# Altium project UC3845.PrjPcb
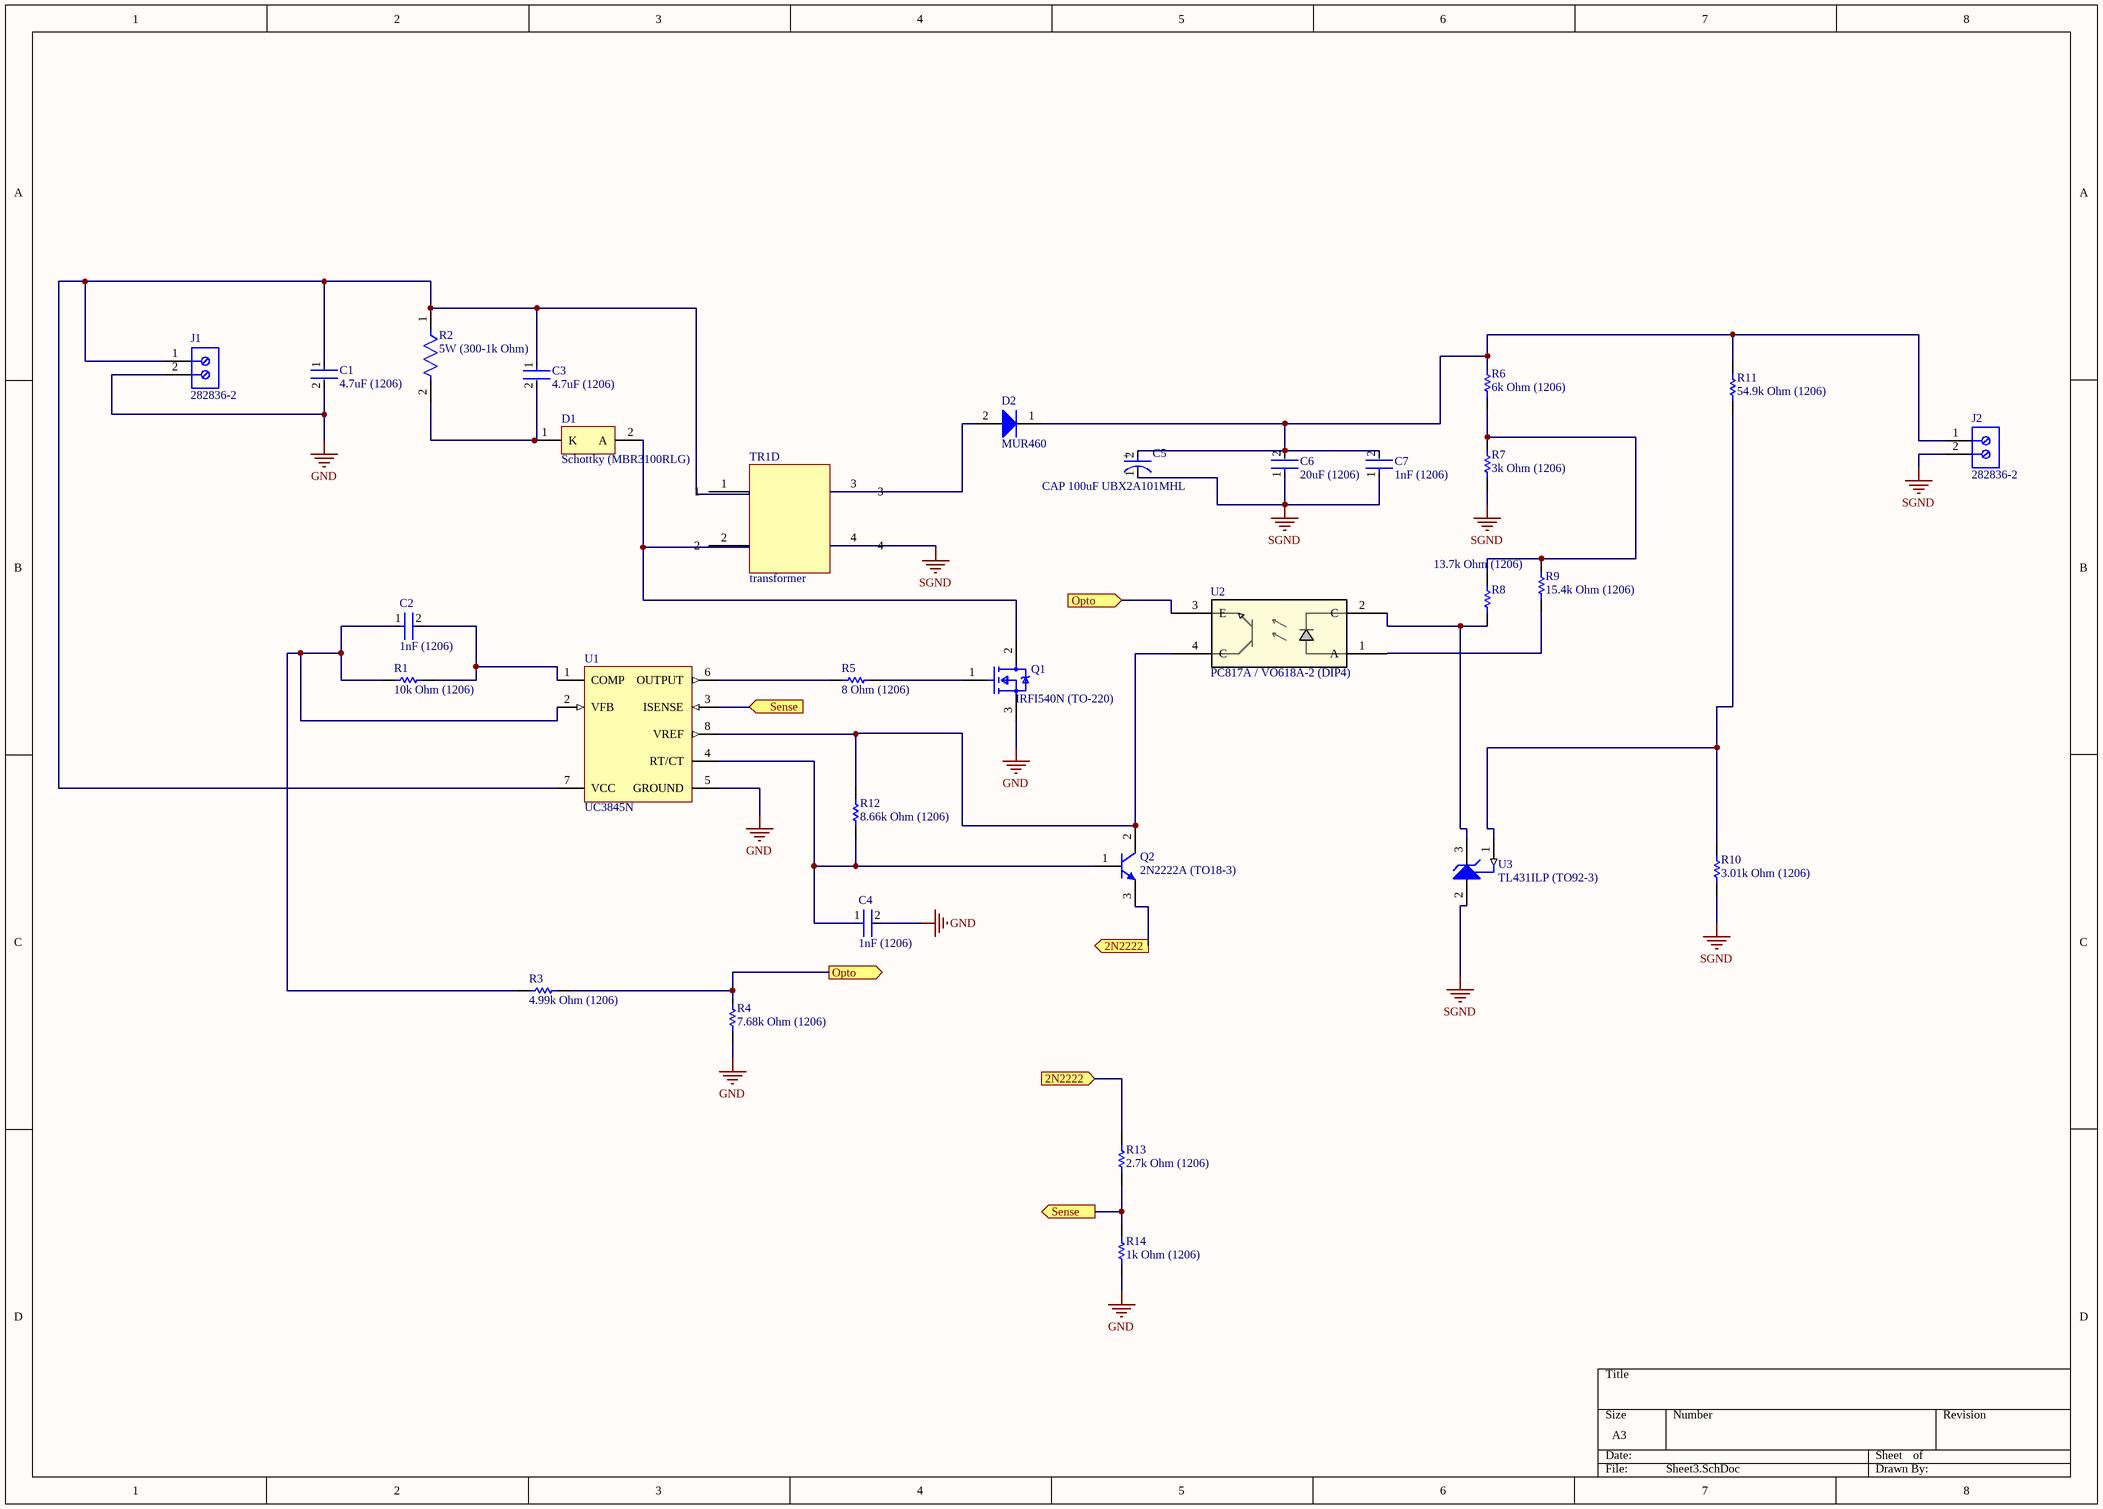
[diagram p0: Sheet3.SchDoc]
1 sheet, 31 parts. Net scope: flat (ports and power ports of the same name join across sheets).
Board file: PCB_v2.PcbDoc

## Sheet Sheet3.SchDoc
size A3

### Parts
C1  4.7uF (1206)  [FP-C1206C-EB-MFG]
C2  1nF (1206)  [FP-C1206C-EB-MFG]
C3  4.7uF (1206)  [FP-C1206C-EB-MFG]
C4  1nF (1206)  [FP-C1206C-EB-MFG]
C5  CAP 100uF UBX2A101MHL  [FP-UBX2A101MHL-MFG]
C6  20uF (1206)  [FP-C1206C-EB-MFG]
C7  1nF (1206)  [FP-C1206C-EB-MFG]
D1  Schottky (MBR3100RLG)  [ONSC-AXIAL_LEAD-2-267-05_V]
D2  MUR460  [ONSC-AXIAL_LEAD-2-267-05_V]
J1  282836-2  [TECO-282836-2_V]
J2  282836-2  [TECO-282836-2_V]
Q1  IRFI540N (TO-220)  [FP-PG-TO220-3-MFG]
Q2  2N2222A (TO18-3)  [STM-TO-18-3]
R1  10k Ohm (1206)  [RESC3216X60X45NL10T20]
R2  5W (300-1k Ohm)  [FP-SQP500-MFG]
R3  4.99k Ohm (1206)  [RESC3216X60X45NL10T20]
R4  7.68k Ohm (1206)  [RESC3216X60X45NL10T20]
R5  8 Ohm (1206)  [RESC3216X60X45NL10T20]
R6  6k Ohm (1206)  [RESC3216X60X45NL10T20]
R7  3k Ohm (1206)  [RESC3216X60X45NL10T20]
R8  13.7k Ohm (1206)  [RESC3216X60X45NL10T20]
R9  15.4k Ohm (1206)  [RESC3216X60X45NL10T20]
R10  3.01k Ohm (1206)  [RESC3216X60X45NL10T20]
R11  54.9k Ohm (1206)  [RESC3216X60X45NL10T20]
R12  8.66k Ohm (1206)  [RESC3216X60X45NL10T20]
R13  2.7k Ohm (1206)  [RESC3216X60X45NL10T20]
R14  1k Ohm (1206)  [RESC3216X60X45NL10T20]
TR1  transformer  [Transformer_flyback]  (part D of 4)
U1  UC3845N  [P0008A]
U2  PC817A / VO618A-2 (DIP4)  [DIP-4_VO618A_VIS]
U3  TL431ILP (TO92-3)  [LP0003A]

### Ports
2N2222 (in), 2N2222 (out), Opto (in), Opto (out), Sense (in), Sense (out)

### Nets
GND: C1.2 C4.2 J1.2 Q1.3(S) R4.1 R14.1 U1.5(GROUND)
SGND: C5.1(C) C6.1 C7.1 J2.2 R7.2 R10.2 TR1.4 U3.2(ANODE)
NetC1_1: C1.1 C3.1 J1.1 R2.1 TR1.1 U1.7(VCC)
NetC2_1: C2.1 R1.2 R3.2 U1.2(VFB)
NetC2_2: C2.2 R1.1 U1.1(COMP)
NetC3_2: C3.2 D1.1(K) R2.2
NetC4_1: C4.1 Q2.1(B) R12.2 U1.4(RT/CT)
NetC5_2: C5.2(A) C6.2 C7.2 D2.1(K) J2.1 R6.1 R11.1
NetD1_2: D1.2(A) Q1.2(D) TR1.2
NetD2_2: D2.2(A) TR1.3
NetQ1_1: Q1.1(G) R5.1
NetQ2_2: Q2.2(C) R12.1 U1.8(VREF) U2.4(C)
NetQ2_3: Q2.3(E) R13.1 ; port 2N2222
NetR3_1: R3.1 R4.2 U2.3(E) ; port Opto
NetR5_2: R5.2 U1.6(OUTPUT)
NetR6_2: R6.2 R7.1 R8.1 R9.1
NetR8_2: R8.2 U2.2(C) U3.3(CATHODE)
NetR9_2: R9.2 U2.1(A)
NetR10_1: R10.1 R11.2 U3.1(REF)
NetR13_2: R13.2 R14.2 U1.3(ISENSE) ; port Sense

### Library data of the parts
C1-C4 C6 C7 = CMP-03020-000955-1: Multilayer Ceramic Capacitor, C Series, 1000 Pf, - 5%, C0g / Np0, 100 V, 1206 [3216 Metric] Rohs Compliant: Yes; Manufacturer: KEMET; Manufacturer Part Number: C1206C102J1GACTU; Capacitance: 1,000 pF; Voltage Rating: 100 V; Tolerance: 0.05; Automotive Grade: Grade 0; Temperature Coefficient: 15%; Value: 1,000 pF
C5 = CMP-12462-000004-1: CAP ALUM 100UF 20% 100V RADIAL; Manufacturer: Nichicon; Material: Aluminum; Automotive Grade: Grade 0; Ripple Current: 950mA; Leakage Current: 300uA; Life: 1000Hours; Dissipation Factor: 8%
D1 = CMP-1055-00020-1: Rectifier, 2-Pin Axial_Lead, Pb-Free, Tape and Reel; Manufacturer: On Semiconductor; Configuration: Single; IFSM Max (A): 150
D2 = CMP-0902-00067-1: SWITCHMODE(TM) Power Rectifier, 2-Pin Axial_Lead, Pb-Free, Bulk Bag; Manufacturer: On Semiconductor; IFSM Max (A): 110; Type: Ultrafast; VRRM Max (V): 600
J1 J2 = CMP-1684-00017-1: Female Header, Pitch 5 mm, 1 x 2 Position, Height 10 mm, Tail Length 3.5 mm, Rohs, Bulk; Manufacturer: TE Connectivity; Wire Gauge: 16-30AWG; Product Training Modules: Wire-to-BoardEurostyleTerminalBlocks; Clamp Material - Plating: Brass-NickelPlated; Voltage: 300V; Mating Orientation: HorizontalwithBoard; Current: 13.5A; Pitch: 0.197"(5.00mm); Screw Thread: M3; 3D Model: 282836-2.pdf; Other Names: 5ULV-02B / A98076; Dynamic Catalog: BuchananSeries; Number of Levels: 1; Torque - Screw: 0.68Nm(6Lb-In); Featured Product: EurostyleTerminalBlockConnectors; Positions Per Level: 2; Wire Termination: Screw-RisingCageClamp
Q1 = CMP-32901-000575-1: MOSFET N-CH 100V 20A TO220FP; Gate to Source Voltage (Vgs): 20V; Power Dissipation: 54W; Rds On Max: 52mR; Threshold Voltage: 4V; Turn-On Delay Time: 8.2ns; Turn-Off Delay Time: 44ns; Input Capacitance: 1.4nF; Element Configuration: Single
Q2 = CMP-2000-05381-1: High Speed Switch, 0.6 A IC, -65 to 175 degC, 3-Pin TO-18, RoHS, Bulk; Manufacturer: STMicroelectronics; Power Dissipation Pd: 500mW; DC Current Gain hFE: 300hFE; Transistor Polarity: NPN; DC Collector Current: 600mA; No. of Pins: 3Pins; Transition Frequency ft: 300MHz; Collector Emitter Voltage V(br)ceo: 40V
R1 R3-R14 = CMP-2003-02424-1: Manufacturer: Vishay Dale; Part Number: CRCW12068R25FKEA
R2 = CMP-03413-000003-1: Manufacturer Part Number: SQP500JB-1R2; Manufacturer: Yageo; Temperature Coefficient: 300ppm/°C; Resistance: 1.2Ω; Tolerance: 5%; Value: 1.2Ω; Voltage Rating: 350V
U1 = CMP-0319-00305-2: PWM Controller with Current Control, 50 % Duty Cycle, 0 to +70 degC, 8-pin PDIP (P), Green (RoHS & no Sb/Br); Manufacturer: Texas Instruments; Rating: Catalog; UVLO Thresholds On/Off(V): 8.4/7.6; Regulated Outputs(#): 1; Duty Cycle(Max)(%): 50; Frequency(Max)(kHz): 450; Topology: Boost, Buck, Flyback, Forward
U2 = CMP-00030-24929081_03-1: VO618A-2 Optocoupler DC-IN 1-CH Transistor DC-OUT 4-Pin PDIP; Fall Time: 14µs; Output Current per Channel: 50mA; Current Transfer Ratio: 125%; Input Current: 60mA; Collector Emitter Saturation Voltage: 400mV; Reverse Breakdown Voltage: 6V; Rise Time: 3µs; Power Dissipation: 150mW; Isolation Voltage: 5.3kV; Max Output Voltage: 80V; Number of Channels: 1; Forward Voltage: 1.1V
U3 = CMP-0366-00043-2: Adjustable Precision Shunt Regulator, 34 ppm / degC, 100 mA, -40 to 85 degC, 3-pin TO-92 (LP), Pb-Free (RoHS); Manufacturer: Texas Instruments; Iout/Iz(Max)(mA): 100; Rating: Military; Temp Coeff(Typ)(ppm/ degree C): 34; Initial Accuracy @ 25/deg C(%): 2; SubFamily: Shunt Voltage Reference; VO Adj(Max)(V): 36; VO Adj(Min)(V): 2.495; Temp Coeff(Max)(ppm/ degree C): 92; Min Iz for Regulation(uA): 600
